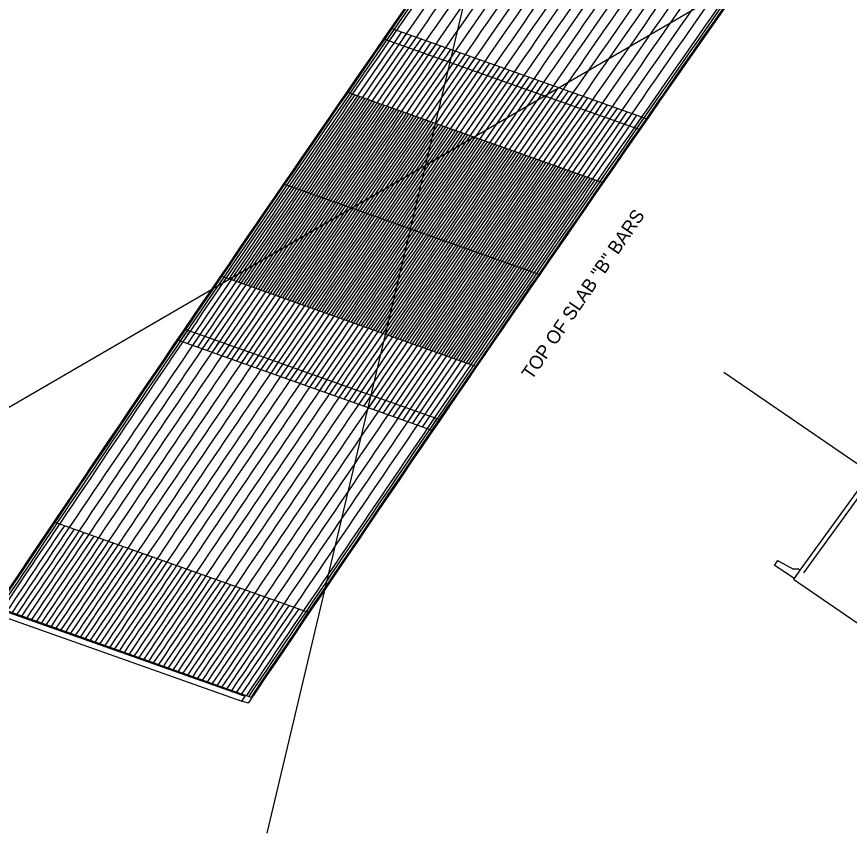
# Model space of a CAD drawing. Extents: x 2378999 to 2381348, y 331302 to 333122.
# Drawn here: x 2379905.9 to 2380030.4, y 332419.5 to 332541.6 of the extents above; entities that cross this region are included whole.
import ezdxf

# ---------------------------------------------------------------- set-up
doc = ezdxf.new("R2010")
doc.units = 0
for name, color, linetype in [('Arrowhead Terminators', 7, 'Continuous'), ('Mis Work Point CELL', 7, 'Continuous'), ('P_SMU_Barrier_Rail', 7, 'Continuous'), ('P_SMU_Concrete_Barrier_Rail', 7, 'Continuous'), ('P_SMU_Mis_Long_Chord', 7, 'Continuous'), ('P_SMU_Rebar_B_Bar', 7, 'Continuous'), ('Scratch_Level_0', 7, 'Continuous'), ('Sup Concrete Slab Lines', 7, 'Continuous'), ('Text', 7, 'Continuous')]:
    doc.layers.add(name, color=color, linetype=linetype)

msp = doc.modelspace()

# ---------------------------------------------------------------- linework, layer by layer
at = {"layer": 'Arrowhead Terminators'}
for radius, start, end in [(7099.13, 144.933691, 145.338143), (7098.75, 144.932847, 145.337324), (7097.25, 144.929472, 145.334043), (7095.75, 144.926095, 145.330761), (7094.25, 144.922716, 145.327478), (7092.75, 144.919336, 145.324193), (7091.25, 144.915954, 145.320907), (7089.75, 144.912571, 145.317619), (7088.25, 144.909187, 145.31433), (7086.75, 144.9058, 145.31104), (7085.25, 144.902413, 145.307748), (7083.75, 144.899024, 145.304454), (7082.25, 144.895633, 145.301159), (7080.75, 144.892241, 145.297863), (7079.25, 144.888848, 145.294565), (7077.75, 144.885453, 145.291266), (7076.25, 144.882056, 145.287965), (7074.75, 144.878658, 145.284663), (7073.25, 144.875259, 145.28136), (7071.75, 144.871858, 145.278055), (7070.25, 144.868455, 145.274748), (7068.75, 144.865051, 145.27144), (7067.25, 144.861645, 145.268131), (7065.75, 144.858238, 145.26482), (7064.25, 144.85483, 145.261508), (7062.75, 144.85142, 145.258194), (7061.25, 144.848008, 145.254879), (7060.88, 144.847155, 145.25405), (7099.13, 145.322674, 145.778676), (7098.75, 145.321854, 145.777879), (7098, 145.320212, 145.776286), (7097.25, 145.31857, 145.774692), (7096.5, 145.316927, 145.773098), (7095.75, 145.315285, 145.771503), (7095, 145.313642, 145.769908), (7094.25, 145.311998, 145.768313), (7093.5, 145.310354, 145.766717), (7092.75, 145.30871, 145.765121), (7092, 145.307066, 145.763525), (7091.25, 145.305421, 145.761928), (7090.5, 145.303775, 145.760331), (7089.75, 145.30213, 145.758734), (7089, 145.300484, 145.757136), (7088.25, 145.298837, 145.755538), (7087.5, 145.297191, 145.75394), (7086.75, 145.295544, 145.752341), (7086, 145.293896, 145.750742), (7085.25, 145.292248, 145.749142), (7084.5, 145.2906, 145.747543), (7083.75, 145.288952, 145.745942), (7083, 145.287303, 145.744342), (7082.25, 145.285653, 145.742741), (7081.5, 145.284004, 145.74114), (7080.75, 145.282354, 145.739538), (7080, 145.280703, 145.737936), (7079.25, 145.279053, 145.736334), (7078.5, 145.277402, 145.734731), (7077.75, 145.27575, 145.733129), (7077, 145.274098, 145.731525), (7076.25, 145.272446, 145.729922), (7075.5, 145.270794, 145.728317), (7074.75, 145.269141, 145.726713), (7074, 145.267488, 145.725108), (7073.25, 145.265834, 145.723503), (7072.5, 145.26418, 145.721898), (7098.38, 145.41453, 145.683586), (7097.63, 145.412898, 145.681982), (7096.88, 145.411265, 145.680378), (7071.75, 145.262526, 145.720292), (7071, 145.260871, 145.718686), (7070.25, 145.259216, 145.717079), (7069.5, 145.25756, 145.715473), (7096.13, 145.409633, 145.678774), (7095.38, 145.408, 145.677169), (7094.63, 145.406366, 145.675564), (7093.88, 145.404732, 145.673959), (7093.13, 145.403098, 145.672353), (7068.75, 145.255905, 145.713865), (7068, 145.254249, 145.712258), (7067.25, 145.252592, 145.71065), (7066.5, 145.250935, 145.709042), (7065.75, 145.249278, 145.707433), (7092.38, 145.401464, 145.670747), (7091.63, 145.399829, 145.669141), (7090.88, 145.398194, 145.667534), (7090.13, 145.396558, 145.665927), (7089.38, 145.394922, 145.66432), (7065, 145.24762, 145.705824), (7064.25, 145.245962, 145.704215), (7063.5, 145.244304, 145.702605), (7062.75, 145.242645, 145.700995), (7062, 145.240986, 145.699385), (7088.63, 145.393286, 145.662712), (7087.88, 145.391649, 145.661104), (7087.13, 145.390012, 145.659495), (7086.38, 145.388375, 145.657886), (7085.63, 145.386737, 145.656277), (7061.25, 145.239327, 145.697774), (7060.88, 145.238497, 145.696969), (7084.88, 145.385099, 145.654668), (7084.13, 145.383461, 145.653058), (7083.38, 145.381822, 145.651447), (7082.63, 145.380183, 145.649837), (7081.88, 145.378543, 145.648226), (7081.13, 145.376903, 145.646615), (7080.38, 145.375263, 145.645003), (7079.63, 145.373623, 145.643391), (7078.88, 145.371982, 145.641778), (7078.13, 145.37034, 145.640166), (7077.38, 145.368699, 145.638553), (7076.63, 145.367057, 145.636939), (7075.88, 145.365414, 145.635325), (7075.13, 145.363771, 145.633711), (7074.38, 145.362128, 145.632097), (7073.63, 145.360485, 145.630482), (7072.88, 145.358841, 145.628867), (7072.13, 145.357197, 145.627251), (7071.38, 145.355552, 145.625635), (7070.63, 145.353907, 145.624019), (7069.88, 145.352262, 145.622402), (7069.13, 145.350616, 145.620785), (7068.38, 145.34897, 145.619168), (7067.63, 145.347324, 145.61755), (7066.88, 145.345677, 145.615932), (7066.13, 145.34403, 145.614314), (7065.38, 145.342383, 145.612695), (7064.63, 145.340735, 145.611076), (7063.88, 145.339087, 145.609456), (7063.13, 145.337438, 145.607837), (7062.38, 145.335789, 145.606216), (7061.63, 145.33414, 145.604596), (7099.13, 145.763207, 146.167718), (7098.75, 145.762409, 146.166944), (7097.25, 145.759219, 146.163848), (7095.75, 145.756027, 146.16075), (7094.25, 145.752833, 146.157651), (7092.75, 145.749638, 146.154551), (7091.25, 145.746442, 146.15145), (7089.75, 145.743244, 146.148347), (7088.25, 145.740045, 146.145242), (7086.75, 145.736845, 146.142136), (7085.25, 145.733643, 146.139029), (7083.75, 145.73044, 146.135921), (7082.25, 145.727235, 146.132811), (7080.75, 145.724029, 146.1297), (7079.25, 145.720822, 146.126588), (7077.75, 145.717613, 146.123474), (7076.25, 145.714402, 146.120359), (7074.75, 145.711191, 146.117242), (7073.25, 145.707978, 146.114124), (7071.75, 145.704763, 146.111005), (7070.25, 145.701547, 146.107884), (7068.75, 145.69833, 146.104762), (7067.25, 145.695111, 146.101638), (7065.75, 145.691891, 146.098514), (7064.25, 145.688669, 146.095388), (7062.75, 145.685446, 146.09226), (7061.25, 145.682222, 146.089131), (7060.88, 145.681416, 146.088349), (7098, 146.041624, 146.165396), (7096.5, 146.038501, 146.162299), (7095, 146.035377, 146.159201), (7093.5, 146.032251, 146.156101), (7092, 146.029124, 146.153), (7090.5, 146.025995, 146.149898), (7089, 146.022865, 146.146795), (7087.5, 146.019734, 146.14369), (7086, 146.016601, 146.140583), (7084.5, 146.013467, 146.137475), (7083, 146.010332, 146.134366), (7081.5, 146.007195, 146.131256), (7080, 146.004057, 146.128144), (7078.5, 146.000918, 146.125031), (7077, 145.997777, 146.121916), (7075.5, 145.994635, 146.1188), (7074, 145.991491, 146.115683), (7072.5, 145.988346, 146.112564), (7071, 145.9852, 146.109444), (7069.5, 145.982052, 146.106323), (7068, 145.978903, 146.1032), (7066.5, 145.975752, 146.100076), (7065, 145.9726, 146.096951), (7063.5, 145.969447, 146.093824), (7062, 145.966293, 146.090696)]:
    msp.add_arc((2385800.44, 328500.58), radius, start, end, dxfattribs=at)
at = {"layer": 'Mis Work Point CELL'}
msp.add_line((2379945.82, 332516.57), (2379984.13, 332503.01), dxfattribs=at)
at = {"layer": 'P_SMU_Barrier_Rail'}
for p, q in [((2380019.28, 332459.58), (2380019.69, 332460.18)), ((2380019.29, 332459.52), (2380019.28, 332459.58)), ((2380022.14, 332457.56), (2380019.29, 332459.52)), ((2380019.75, 332460.19), (2380019.69, 332460.18)), ((2380019.75, 332460.19), (2380022.07, 332458.93)), ((2380022.78, 332458.94), (2380022.07, 332458.93)), ((2380022.99, 332458.8), (2380022.78, 332458.94))]:
    msp.add_line(p, q, dxfattribs=at)
at = {"layer": 'P_SMU_Concrete_Barrier_Rail'}
for p, q in [((2380044.12, 332487.96), (2380022.99, 332458.8)), ((2380044.66, 332487.57), (2380023.53, 332458.41)), ((2380022.99, 332458.8), (2380022.14, 332457.56)), ((2380022.14, 332457.56), (2380022.07, 332457.46)), ((2380022.07, 332457.46), (2380044.35, 332442.15)), ((2379903.75, 332452.82), (2379940.08, 332439.96)), ((2379939.44, 332440.19), (2379940.08, 332439.96)), ((2379939.6, 332439.24), (2379940.08, 332439.96)), ((2379940.54, 332438.91), (2379939.6, 332439.24))]:
    msp.add_line(p, q, dxfattribs=at)
for radius, start, end in [(7099.63, 144.926438, 146.177079), (7060.38, 144.837589, 146.095684)]:
    msp.add_arc((2385800.44, 328500.58), radius, start, end, dxfattribs=at)
at = {"layer": 'P_SMU_Mis_Long_Chord'}
msp.add_line((2380011.64, 332488.43), (2380055.46, 332458.32), dxfattribs=at)
at = {"layer": 'P_SMU_Rebar_B_Bar'}
msp.add_line((2379903.27, 332452.1), (2379939.6, 332439.24), dxfattribs=at)
at = {"layer": 'Scratch_Level_0'}
for p, q in [((2379962.01, 332539.77), (2380000.03, 332526.31)), ((2379960.92, 332538.2), (2379998.93, 332524.73)), ((2379993.43, 332516.78), (2379955.43, 332530.24)), ((2379936.57, 332502.75), (2379974.53, 332489.32)), ((2379969.08, 332481.34), (2379931.13, 332494.77)), ((2379930.05, 332493.18), (2379968, 332479.76)), ((2379911.63, 332465.96), (2379949.52, 332452.54)), ((2379903.08, 332453.23), (2379940.95, 332439.83))]:
    msp.add_line(p, q, dxfattribs=at)
for radius, start, end in [(7099.46, 144.934441, 146.168406), (7060.54, 144.846397, 146.087653)]:
    msp.add_arc((2385800.44, 328500.58), radius, start, end, dxfattribs=at)
at = {"layer": 'Text'}
for p, q in [((2379943.39, 332419.46), (2379989.44, 332613.71)), ((2380040.39, 332561.96), (2379898.66, 332479.61))]:
    msp.add_line(p, q, dxfattribs=at)

# ---------------------------------------------------------------- texts
at = {"layer": 'Sup Concrete Slab Lines'}
msp.add_text('TOP OF SLAB "B" BARS', height=2, rotation=55.5093, dxfattribs=at).set_placement((2379982.92, 332487.13))

doc.saveas('drawing.dxf')
